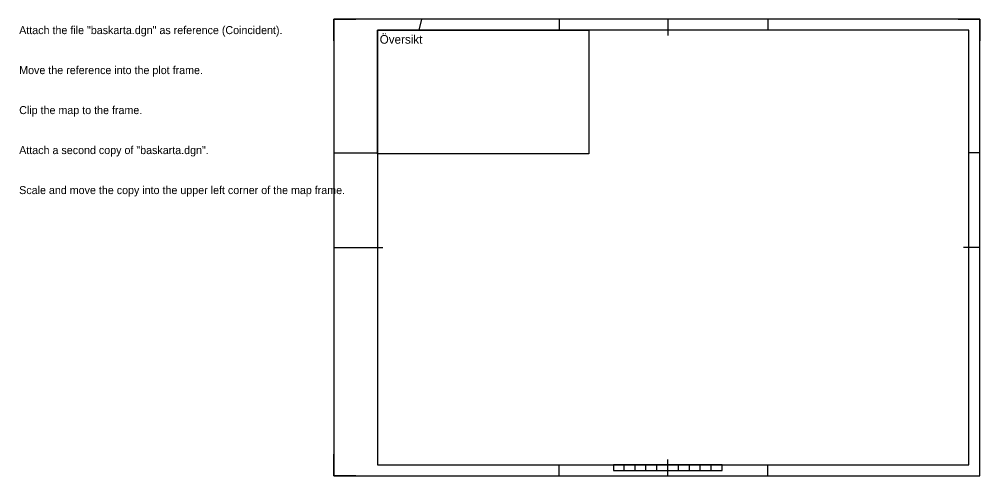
# Model space of a CAD drawing. Extents: x 1517807 to 1518690, y 6495176 to 6495596.
import ezdxf

# ---------------------------------------------------------------- set-up
doc = ezdxf.new("R2010")
doc.units = 0
for name, color, linetype in [('Instruktioner', 7, 'Continuous'), ('Plotshape', 7, 'Continuous'), ('S130', 7, 'Continuous')]:
    doc.layers.add(name, color=color, linetype=linetype)

msp = doc.modelspace()

# ---------------------------------------------------------------- linework, layer by layer
at = {"layer": 'Plotshape'}
msp.add_lwpolyline([(1518096.01, 6495176.1), (1518690.01, 6495176.1), (1518690.01, 6495596.1), (1518096.01, 6495596.1)], close=True, dxfattribs=at)
at = {"layer": 'S130'}
for p, q in [((1518096.01, 6495576.1), (1518096.01, 6495596.1)), ((1518096.01, 6495596.1), (1518116.01, 6495596.1)), ((1518176.67, 6495596.1), (1518173.97, 6495586.1)), ((1518303.01, 6495596.1), (1518303.01, 6495586.1)), ((1518403.01, 6495596.1), (1518403.01, 6495581.1)), ((1518495.01, 6495596.1), (1518495.01, 6495586.1)), ((1518670.01, 6495596.1), (1518690.01, 6495596.1)), ((1518690.01, 6495596.1), (1518690.01, 6495576.1)), ((1518096.01, 6495473.1), (1518136.01, 6495473.1)), ((1518690.01, 6495473.1), (1518680.01, 6495473.1)), ((1518096.01, 6495386.1), (1518141.01, 6495386.1)), ((1518690.01, 6495386.1), (1518675.01, 6495386.1)), ((1518096.01, 6495176.1), (1518096.01, 6495196.1)), ((1518690.01, 6495176.1), (1518690.01, 6495196.1)), ((1518303.01, 6495176.1), (1518303.01, 6495186.1)), ((1518362.96, 6495181.1), (1518362.96, 6495186.1)), ((1518372.96, 6495181.1), (1518372.96, 6495186.1)), ((1518382.96, 6495181.1), (1518382.96, 6495186.1)), ((1518392.96, 6495181.1), (1518392.96, 6495186.1)), ((1518402.96, 6495181.1), (1518402.96, 6495186.1)), ((1518403.01, 6495176.1), (1518403.01, 6495191.1)), ((1518412.96, 6495181.1), (1518412.96, 6495186.1)), ((1518422.96, 6495181.1), (1518422.96, 6495186.1)), ((1518432.96, 6495181.1), (1518432.96, 6495186.1)), ((1518442.96, 6495181.1), (1518442.96, 6495186.1)), ((1518495.01, 6495176.1), (1518495.01, 6495186.1)), ((1518116.01, 6495176.1), (1518096.01, 6495176.1)), ((1518670.01, 6495176.1), (1518690.01, 6495176.1))]:
    msp.add_line(p, q, dxfattribs=at)
for points in [[(1518136.01, 6495186.1), (1518680.01, 6495186.1), (1518680.01, 6495586.1), (1518136.01, 6495586.1)], [(1518136.01, 6495586.1), (1518330.46, 6495586.1), (1518330.46, 6495472.2), (1518136.01, 6495472.2)], [(1518353.01, 6495181.1), (1518453.01, 6495181.1), (1518453.01, 6495186.1), (1518353.01, 6495186.1)]]:
    msp.add_lwpolyline(points, close=True, dxfattribs=at)

# ---------------------------------------------------------------- texts
at = {"layer": 'Instruktioner'}
for s, p in [('Attach the file "baskarta.dgn" as reference (Coincident).', (1517806.54, 6495582.39)), ('Move the reference into the plot frame.', (1517806.54, 6495545.6)), ('Clip the map to the frame.', (1517806.54, 6495508.81)), ('Attach a second copy of "baskarta.dgn".', (1517806.54, 6495472.02)), ('Scale and move the copy into the upper left corner of the map frame.', (1517806.54, 6495435.23))]:
    msp.add_text(s, height=7.3579, dxfattribs=at).set_placement(p)
at = {"layer": 'S130'}
msp.add_text('Översikt', height=8, dxfattribs=at).set_placement((1518138.11, 6495573.55))

doc.saveas('drawing.dxf')
